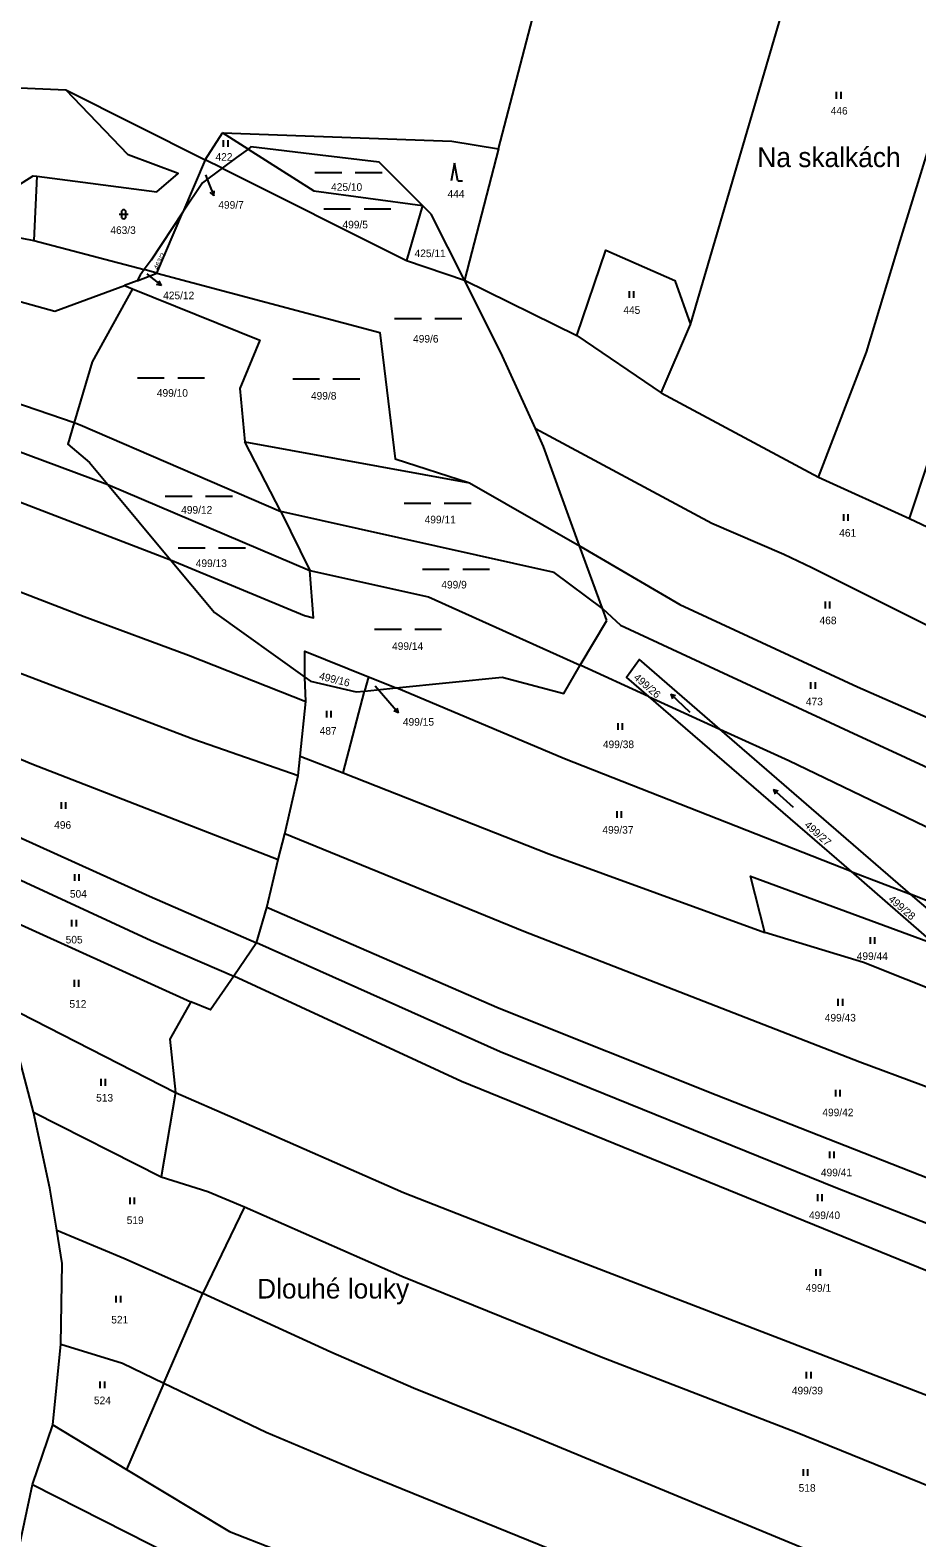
# Model space of a CAD drawing. Extents: x -751333 to -746055, y -1133395 to -1129777.
# Drawn here: x -748639.3 to -748441, y -1130763.6 to -1130426.4 of the extents above; entities that cross this region are included whole.
import ezdxf

# ---------------------------------------------------------------- set-up
doc = ezdxf.new("R2010")
doc.units = 0
for name, color, linetype in [('Hranice parcel', 7, 'Continuous'), ('Parcelní čísla', 7, 'Continuous'), ('Pop  PČ popisy', 7, 'Continuous'), ('Značky kultur', 7, 'Continuous')]:
    doc.layers.add(name, color=color, linetype=linetype)

msp = doc.modelspace()

# ---------------------------------------------------------------- linework, layer by layer
at = {"layer": 'Hranice parcel'}
for p, q in [((-748534.52, -1130452.93), (-748526.93, -1130423.75)), ((-748631.31, -1130439.73), (-748600.12, -1130455.36)), ((-748600.12, -1130455.36), (-748596.26, -1130449.29)), ((-748590.55, -1130452.94), (-748596.26, -1130449.29)), ((-748589.92, -1130452.46), (-748590.55, -1130452.94)), ((-748534.52, -1130452.93), (-748542.15, -1130482.28)), ((-748600.12, -1130455.36), (-748605.1, -1130467.06)), ((-748596.34, -1130457.26), (-748600.12, -1130455.36)), ((-748637.75, -1130459.01), (-748638.43, -1130473.4)), ((-748596.34, -1130457.26), (-748555.14, -1130477.91)), ((-748551.51, -1130465.56), (-748555.14, -1130477.91)), ((-748549.6, -1130467.48), (-748551.51, -1130465.56)), ((-748664.43, -1130468.41), (-748638.43, -1130473.4)), ((-748610.91, -1130480.71), (-748605.1, -1130467.06)), ((-748542.15, -1130482.28), (-748549.6, -1130467.48)), ((-748638.43, -1130473.4), (-748613.76, -1130479.92)), ((-748610.91, -1130480.71), (-748613.76, -1130479.92)), ((-748555.14, -1130477.91), (-748542.15, -1130482.28)), ((-748615.34, -1130482.41), (-748618.21, -1130483.5)), ((-748618.21, -1130483.5), (-748616.35, -1130484.25)), ((-748615.34, -1130482.41), (-748610.91, -1130480.71)), ((-748542.15, -1130482.28), (-748517.05, -1130494.67)), ((-748534, -1130498.43), (-748542.15, -1130482.28)), ((-748616.35, -1130484.25), (-748625.37, -1130500.52)), ((-748498.16, -1130507.52), (-748491.6, -1130492.22)), ((-748517.05, -1130494.67), (-748498.16, -1130507.52)), ((-748625.37, -1130500.52), (-748629.43, -1130514.15)), ((-748526.29, -1130515.48), (-748534, -1130498.43)), ((-748498.16, -1130507.52), (-748462.95, -1130526.39)), ((-748524.47, -1130519.52), (-748526.29, -1130515.48)), ((-748591.26, -1130518.45), (-748541.05, -1130527.62)), ((-748583.24, -1130534.05), (-748591.26, -1130518.45)), ((-748516.42, -1130541.69), (-748524.47, -1130519.52)), ((-748625.99, -1130523.1), (-748621.93, -1130527.97)), ((-748541.05, -1130527.62), (-748516.42, -1130541.69)), ((-748462.95, -1130526.39), (-748442.63, -1130535.63)), ((-748621.93, -1130527.97), (-748576.71, -1130547.24)), ((-748621.93, -1130527.97), (-748607.86, -1130544.88)), ((-748583.24, -1130534.05), (-748576.71, -1130547.24)), ((-748442.63, -1130535.63), (-748423.83, -1130544.43)), ((-748511.31, -1130555.77), (-748516.42, -1130541.69)), ((-748607.86, -1130544.88), (-748598.07, -1130556.63)), ((-748598.07, -1130556.63), (-748577.87, -1130571.1)), ((-748510.34, -1130558.44), (-748511.31, -1130555.77)), ((-748516.24, -1130568.44), (-748510.34, -1130558.44)), ((-748577.63, -1130576.56), (-748577.87, -1130571.1)), ((-748563.63, -1130571.01), (-748564.53, -1130574.23)), ((-748563.63, -1130571.01), (-748557.39, -1130573.5)), ((-748557.39, -1130573.5), (-748533.74, -1130571.13)), ((-748501.01, -1130575.41), (-748516.24, -1130568.44)), ((-748569.31, -1130592.51), (-748564.53, -1130574.23)), ((-748566.33, -1130574.4), (-748564.53, -1130574.23)), ((-748564.53, -1130574.23), (-748557.39, -1130573.5)), ((-748578.87, -1130588.74), (-748577.63, -1130576.56)), ((-748501.01, -1130575.41), (-748485.04, -1130582.73)), ((-748501.01, -1130575.41), (-748455.69, -1130614.55)), ((-748442.43, -1130619.67), (-748485.04, -1130582.73)), ((-748579.32, -1130593.13), (-748578.87, -1130588.74)), ((-748578.87, -1130588.74), (-748569.31, -1130592.51)), ((-748582.3, -1130606.18), (-748579.32, -1130593.13)), ((-748583.8, -1130611.89), (-748582.3, -1130606.18)), ((-748586.34, -1130622.61), (-748583.8, -1130611.89)), ((-748455.69, -1130614.55), (-748442.43, -1130619.67)), ((-748455.69, -1130614.55), (-748437.09, -1130630.78)), ((-748655.15, -1130620.24), (-748603.37, -1130643.75)), ((-748422.31, -1130636.78), (-748442.43, -1130619.67)), ((-748588.68, -1130630.55), (-748586.34, -1130622.61)), ((-748588.68, -1130630.55), (-748593.74, -1130637.98)), ((-748644.81, -1130644.52), (-748606.79, -1130664)), ((-748638.54, -1130668.43), (-748644.81, -1130644.52)), ((-748606.79, -1130664), (-748609.99, -1130682.87)), ((-748638.54, -1130668.43), (-748609.99, -1130682.87)), ((-748591.33, -1130689.59), (-748600.62, -1130708.93)), ((-748609.37, -1130729.04), (-748600.62, -1130708.93)), ((-748634.19, -1130738.36), (-748632.44, -1130720.29)), ((-748609.37, -1130729.04), (-748617.75, -1130748.36)), ((-748638.72, -1130751.72), (-748634.19, -1130738.36)), ((-748634.19, -1130738.36), (-748617.75, -1130748.36)), ((-748641.83, -1130766.14), (-748638.72, -1130751.72))]:
    msp.add_line(p, q, dxfattribs=at)
for points in [[(-748491.6, -1130492.22), (-748475.41, -1130437.09), (-748455.96, -1130370.65), (-748448.4, -1130345.8)], [(-748462.95, -1130526.39), (-748452.24, -1130498.41), (-748444.7, -1130473.49), (-748437.34, -1130449.55), (-748416.99, -1130383.85)], [(-748442.63, -1130535.63), (-748421.81, -1130472.84), (-748398.74, -1130399.57)], [(-748661.8, -1130465.15), (-748676.09, -1130437.74), (-748631.31, -1130439.73)], [(-748637.75, -1130459.01), (-748610.97, -1130462.51), (-748606.2, -1130458.41), (-748617.37, -1130454.25), (-748631.31, -1130439.73)], [(-748596.26, -1130449.29), (-748544.94, -1130451.18), (-748534.52, -1130452.93)], [(-748590.55, -1130452.94), (-748593.13, -1130454.85), (-748596.34, -1130457.26)], [(-748590.55, -1130452.94), (-748575.86, -1130462.3), (-748551.51, -1130465.56)], [(-748551.51, -1130465.56), (-748561.19, -1130455.89), (-748574.39, -1130454.31), (-748589.92, -1130452.46)], [(-748661.8, -1130465.15), (-748649.27, -1130465.67), (-748638.63, -1130458.96), (-748637.75, -1130459.01)], [(-748596.34, -1130457.26), (-748600.74, -1130460.52), (-748605.1, -1130467.06)], [(-748605.1, -1130467.06), (-748612.24, -1130477.79), (-748613.76, -1130479.92)], [(-748517.05, -1130494.67), (-748510.5, -1130475.55), (-748495.1, -1130482.38), (-748491.6, -1130492.22)], [(-748761.98, -1130479.13), (-748710.91, -1130496.25), (-748679.26, -1130506.7), (-748621.93, -1130527.97)], [(-748671.7, -1130478.68), (-748633.74, -1130489.24), (-748618.21, -1130483.5)], [(-748613.76, -1130479.92), (-748614.66, -1130481.2), (-748615.34, -1130482.41)], [(-748610.91, -1130480.71), (-748561.08, -1130494.01), (-748557.67, -1130522.23), (-748541.05, -1130527.62)], [(-748718.34, -1130483.88), (-748698.29, -1130490.59), (-748629.43, -1130514.15)], [(-748616.35, -1130484.25), (-748587.89, -1130495.71), (-748592.35, -1130506.49), (-748591.26, -1130518.45)], [(-748765.12, -1130487.78), (-748722.68, -1130502.34), (-748682.4, -1130515.73), (-748650.26, -1130528.57), (-748607.86, -1130544.88)], [(-748769.41, -1130499.53), (-748730.21, -1130516.5), (-748693.83, -1130531.8), (-748627.18, -1130557.56), (-748603.84, -1130566.17), (-748577.63, -1130576.56)], [(-748629.43, -1130514.15), (-748630.86, -1130518.95), (-748625.99, -1130523.1)], [(-748629.43, -1130514.15), (-748628.07, -1130514.66), (-748583.24, -1130534.05)], [(-748775.79, -1130517.06), (-748724.37, -1130538.57), (-748682.28, -1130555.19), (-748652.69, -1130565.92), (-748602.7, -1130584.94), (-748579.32, -1130593.13)], [(-748526.29, -1130515.48), (-748486.84, -1130536.66), (-748470.75, -1130543.61), (-748464.43, -1130546.57), (-748431.07, -1130563.27), (-748388.62, -1130583.11)], [(-748511.31, -1130555.77), (-748522.06, -1130547.66), (-748583.24, -1130534.05)], [(-748516.42, -1130541.69), (-748493.99, -1130554.85), (-748454.25, -1130573.29), (-748413.5, -1130591.12)], [(-748607.86, -1130544.88), (-748577.9, -1130557.3), (-748575.93, -1130557.81), (-748576.71, -1130547.24)], [(-748576.71, -1130547.24), (-748550.2, -1130553.1), (-748516.24, -1130568.44)], [(-748511.31, -1130555.77), (-748507.24, -1130559.45), (-748489.41, -1130567.71), (-748456.16, -1130583.21), (-748418.92, -1130600.37)], [(-748577.87, -1130571.1), (-748577.86, -1130565.29), (-748563.63, -1130571.01)], [(-748485.04, -1130582.73), (-748503.04, -1130567.18), (-748505.94, -1130571.16), (-748501.01, -1130575.41)], [(-748694.25, -1130568.39), (-748656.01, -1130583.36), (-748638.89, -1130590.49), (-748583.8, -1130611.89)], [(-748577.87, -1130571.1), (-748576.59, -1130572.02), (-748566.33, -1130574.4)], [(-748533.74, -1130571.13), (-748519.95, -1130574.72), (-748516.24, -1130568.44)], [(-748455.69, -1130614.55), (-748519.76, -1130589.35), (-748557.39, -1130573.5)], [(-748485.04, -1130582.73), (-748469.61, -1130589.74), (-748431.04, -1130608.33), (-748396.79, -1130621.28), (-748326.64, -1130647.59), (-748273.31, -1130666.87), (-748248.94, -1130675.02), (-748226.83, -1130683.61)], [(-748675.21, -1130591.78), (-748612.59, -1130620.06), (-748588.68, -1130630.55)], [(-748569.31, -1130592.51), (-748523.25, -1130610.65), (-748474.99, -1130628.2)], [(-748663.32, -1130606.39), (-748612.22, -1130630.04), (-748593.74, -1130637.98)], [(-748370.74, -1130688.16), (-748390.16, -1130680.44), (-748399.18, -1130677.54), (-748453.71, -1130657.26), (-748528.86, -1130627.98), (-748582.3, -1130606.18)], [(-748474.99, -1130628.2), (-748478.16, -1130615.62), (-748437.09, -1130630.78)], [(-748280.18, -1130682.27), (-748326.88, -1130664.57), (-748359.23, -1130651.59), (-748396.02, -1130637.54), (-748426.83, -1130625.94), (-748442.43, -1130619.67)], [(-748340.95, -1130721.23), (-748371.81, -1130709.41), (-748485.85, -1130664.58), (-748534.39, -1130645.25), (-748586.34, -1130622.61)], [(-748414.36, -1130650.31), (-748452.93, -1130634.95), (-748474.99, -1130628.2)], [(-748337.1, -1130732.95), (-748347.47, -1130729.08), (-748459.12, -1130685.32), (-748534.17, -1130654.92), (-748588.68, -1130630.55)], [(-748593.74, -1130637.98), (-748598.96, -1130645.55), (-748603.37, -1130643.75)], [(-748332.9, -1130745.74), (-748359.6, -1130735.19), (-748427.81, -1130708.36), (-748542.83, -1130661.55), (-748593.74, -1130637.98)], [(-748603.37, -1130643.75), (-748608.06, -1130652.05), (-748606.79, -1130664)], [(-748606.79, -1130664), (-748593.41, -1130669.82), (-748555.79, -1130686.41), (-748521.14, -1130699.97), (-748463.67, -1130722.09), (-748402.55, -1130745.71), (-748322.49, -1130777.44)], [(-748633.32, -1130694.84), (-748634.87, -1130685.4), (-748638.54, -1130668.43)], [(-748609.99, -1130682.87), (-748599.51, -1130686.16), (-748591.33, -1130689.59)], [(-748591.33, -1130689.59), (-748556.18, -1130705.09), (-748511.54, -1130723.13), (-748468.11, -1130739.92), (-748424.93, -1130757.48), (-748407.79, -1130764.49), (-748381.4, -1130774.63), (-748330.32, -1130793.51), (-748323.6, -1130795.85)], [(-748633.32, -1130694.84), (-748618.36, -1130701.09), (-748600.62, -1130708.93)], [(-748632.44, -1130720.29), (-748632.1, -1130702.29), (-748633.32, -1130694.84)], [(-748600.62, -1130708.93), (-748572.02, -1130722.05), (-748553.57, -1130730.11), (-748529.63, -1130739.69), (-748429.06, -1130781.38), (-748394.01, -1130795.35), (-748336, -1130816.73)], [(-748632.44, -1130720.29), (-748618.62, -1130724.53), (-748609.37, -1130729.04)], [(-748609.37, -1130729.04), (-748586.47, -1130739.97), (-748565.25, -1130748.92), (-748478.86, -1130784.11), (-748430.59, -1130803.91), (-748354.99, -1130834.29)], [(-748617.75, -1130748.36), (-748594.66, -1130762.19), (-748574.85, -1130769.98), (-748508.41, -1130796.48), (-748448.56, -1130820.81), (-748391.34, -1130844.41), (-748350.77, -1130860.5)], [(-748638.72, -1130751.72), (-748602.16, -1130770.3), (-748522.97, -1130802.41), (-748472.42, -1130822.39), (-748429.14, -1130840.54), (-748407.16, -1130849.74), (-748367.71, -1130867.32)]]:
    msp.add_lwpolyline(points, dxfattribs=at)
at = {"layer": 'Pop  PČ popisy'}
for p, q in [((-748600.09, -1130458.74), (-748599.31, -1130460.66)), ((-748599.31, -1130460.66), (-748598.186, -1130463.442)), ((-748598.186, -1130463.442), (-748599.025, -1130462.702)), ((-748598.186, -1130463.442), (-748598.097, -1130462.326)), ((-748613.2, -1130480.86), (-748612.28, -1130481.59)), ((-748612.28, -1130481.59), (-748609.915, -1130483.438)), ((-748609.915, -1130483.438), (-748611.013, -1130483.216)), ((-748609.915, -1130483.438), (-748610.396, -1130482.426)), ((-748562.13, -1130573), (-748558.86, -1130576.82)), ((-748558.86, -1130576.82), (-748556.891, -1130579.085)), ((-748556.891, -1130579.085), (-748557.17, -1130578.001)), ((-748556.891, -1130579.085), (-748557.926, -1130578.658))]:
    msp.add_line(p, q, dxfattribs=at)
at = {"layer": 'Značky kultur'}
for p, q in [((-748458.931, -1130441.68), (-748458.931, -1130440.18)), ((-748457.93, -1130441.68), (-748457.93, -1130440.18)), ((-748596.011, -1130452.49), (-748596.011, -1130450.99)), ((-748595.01, -1130452.49), (-748595.01, -1130450.99)), ((-748544.37, -1130456.08), (-748545.12, -1130460.08)), ((-748543.62, -1130460.08), (-748544.37, -1130456.08)), ((-748575.589, -1130458.19), (-748569.589, -1130458.19)), ((-748566.589, -1130458.19), (-748560.589, -1130458.19)), ((-748543.62, -1130460.08), (-748542.624, -1130460.08)), ((-748573.609, -1130466.35), (-748567.609, -1130466.35)), ((-748564.609, -1130466.35), (-748558.609, -1130466.35)), ((-748619.361, -1130467.541), (-748617.359, -1130467.541)), ((-748618.861, -1130467.041), (-748618.861, -1130468.042)), ((-748617.859, -1130468.042), (-748617.859, -1130467.041)), ((-748505.261, -1130486.27), (-748505.261, -1130484.77)), ((-748504.26, -1130486.27), (-748504.26, -1130484.77)), ((-748557.769, -1130490.84), (-748551.769, -1130490.84)), ((-748548.769, -1130490.84), (-748542.769, -1130490.84)), ((-748615.269, -1130504.15), (-748609.269, -1130504.15)), ((-748606.269, -1130504.15), (-748600.269, -1130504.15)), ((-748580.559, -1130504.37), (-748574.559, -1130504.37)), ((-748571.559, -1130504.37), (-748565.559, -1130504.37)), ((-748609.059, -1130530.57), (-748603.059, -1130530.57)), ((-748600.059, -1130530.57), (-748594.059, -1130530.57)), ((-748555.669, -1130532.17), (-748549.669, -1130532.17)), ((-748546.669, -1130532.17), (-748540.669, -1130532.17)), ((-748457.331, -1130536.12), (-748457.331, -1130534.62)), ((-748456.33, -1130536.12), (-748456.33, -1130534.62)), ((-748606.149, -1130542.13), (-748600.149, -1130542.13)), ((-748597.149, -1130542.13), (-748591.149, -1130542.13)), ((-748551.549, -1130546.92), (-748545.549, -1130546.92)), ((-748542.549, -1130546.92), (-748536.549, -1130546.92)), ((-748461.411, -1130555.7), (-748461.411, -1130554.2)), ((-748460.41, -1130555.7), (-748460.41, -1130554.2)), ((-748562.259, -1130560.36), (-748556.259, -1130560.36)), ((-748553.259, -1130560.36), (-748547.259, -1130560.36)), ((-748491.643, -1130578.988), (-748496.031, -1130574.896)), ((-748496.031, -1130574.896), (-748495.658, -1130575.929)), ((-748496.031, -1130574.896), (-748494.974, -1130575.196)), ((-748464.671, -1130573.74), (-748464.671, -1130572.24)), ((-748463.67, -1130573.74), (-748463.67, -1130572.24)), ((-748572.941, -1130580.1), (-748572.941, -1130578.6)), ((-748571.94, -1130580.1), (-748571.94, -1130578.6)), ((-748507.791, -1130582.87), (-748507.791, -1130581.37)), ((-748506.79, -1130582.87), (-748506.79, -1130581.37)), ((-748468.578, -1130600.25), (-748473.036, -1130596.235)), ((-748473.036, -1130596.235), (-748472.646, -1130597.261)), ((-748473.036, -1130596.235), (-748471.975, -1130596.516)), ((-748632.291, -1130600.58), (-748632.291, -1130599.08)), ((-748631.29, -1130600.58), (-748631.29, -1130599.08)), ((-748508.031, -1130602.56), (-748508.031, -1130601.06)), ((-748507.03, -1130602.56), (-748507.03, -1130601.06)), ((-748629.281, -1130616.67), (-748629.281, -1130615.17)), ((-748628.28, -1130616.67), (-748628.28, -1130615.17)), ((-748629.941, -1130626.91), (-748629.941, -1130625.41)), ((-748628.94, -1130626.91), (-748628.94, -1130625.41)), ((-748451.361, -1130630.74), (-748451.361, -1130629.24)), ((-748450.36, -1130630.74), (-748450.36, -1130629.24)), ((-748629.371, -1130640.34), (-748629.371, -1130638.84)), ((-748628.37, -1130640.34), (-748628.37, -1130638.84)), ((-748458.551, -1130644.59), (-748458.551, -1130643.09)), ((-748457.55, -1130644.59), (-748457.55, -1130643.09)), ((-748623.391, -1130662.49), (-748623.391, -1130660.99)), ((-748622.39, -1130662.49), (-748622.39, -1130660.99)), ((-748459.111, -1130664.9), (-748459.111, -1130663.4)), ((-748458.11, -1130664.9), (-748458.11, -1130663.4)), ((-748460.461, -1130678.72), (-748460.461, -1130677.22)), ((-748459.46, -1130678.72), (-748459.46, -1130677.22)), ((-748616.921, -1130689.02), (-748616.921, -1130687.52)), ((-748615.92, -1130689.02), (-748615.92, -1130687.52)), ((-748463.131, -1130688.29), (-748463.131, -1130686.79)), ((-748462.13, -1130688.29), (-748462.13, -1130686.79)), ((-748463.531, -1130705.04), (-748463.531, -1130703.54)), ((-748462.53, -1130705.04), (-748462.53, -1130703.54)), ((-748620.011, -1130710.98), (-748620.011, -1130709.48)), ((-748619.01, -1130710.98), (-748619.01, -1130709.48)), ((-748465.621, -1130728), (-748465.621, -1130726.5)), ((-748464.62, -1130728), (-748464.62, -1130726.5)), ((-748623.591, -1130730.19), (-748623.591, -1130728.69)), ((-748622.59, -1130730.19), (-748622.59, -1130728.69)), ((-748466.341, -1130749.77), (-748466.341, -1130748.27)), ((-748465.34, -1130749.77), (-748465.34, -1130748.27))]:
    msp.add_line(p, q, dxfattribs=at)
for centre, start, end in [((-748618.36, -1130467.041), 0, 180), ((-748618.36, -1130468.041), 180, 359.98789)]:
    msp.add_arc(centre, 0.5, start, end, dxfattribs=at)

# ---------------------------------------------------------------- texts
at = {"layer": 'Parcelní čísla'}
for s, p in [('446', (-748460.25, -1130445.23)), ('422', (-748597.82, -1130455.56)), ('425/10', (-748571.97, -1130462.29)), ('444', (-748545.93, -1130463.84)), ('499/7', (-748597.19, -1130466.288)), ('463/3', (-748621.34, -1130471.94)), ('499/5', (-748569.42, -1130470.7)), ('425/11', (-748553.3, -1130477.13)), ('425/12', (-748609.53, -1130486.548)), ('445', (-748506.62, -1130489.82)), ('499/6', (-748553.64, -1130496.24)), ('499/10', (-748610.94, -1130508.36)), ('499/8', (-748576.47, -1130509)), ('499/12', (-748605.5, -1130534.52)), ('499/11', (-748551.05, -1130536.69)), ('461', (-748458.34, -1130539.67)), ('499/13', (-748602.24, -1130546.46)), ('499/9', (-748547.32, -1130551.25)), ('468', (-748462.74, -1130559.25)), ('499/14', (-748558.34, -1130565)), ('473', (-748465.79, -1130577.41)), ('499/15', (-748555.91, -1130581.948)), ('487', (-748574.53, -1130583.95)), ('499/38', (-748511.18, -1130586.97)), ('496', (-748633.9, -1130605.01)), ('499/37', (-748511.3, -1130606.11)), ('504', (-748630.39, -1130620.42)), ('505', (-748631.33, -1130630.67)), ('499/44', (-748454.42, -1130634.35)), ('512', (-748630.49, -1130645.05)), ('499/43', (-748461.57, -1130648.13)), ('513', (-748624.52, -1130666.04)), ('499/42', (-748462.11, -1130669.32)), ('499/41', (-748462.43, -1130682.76)), ('519', (-748617.68, -1130693.44)), ('499/40', (-748465.1, -1130692.33)), ('499/1', (-748465.84, -1130708.59)), ('521', (-748621.13, -1130715.69)), ('499/39', (-748468.93, -1130731.55)), ('524', (-748625.01, -1130733.74)), ('518', (-748467.41, -1130753.32))]:
    msp.add_text(s, height=1.7, dxfattribs=at).set_placement(p)
for s, height, rotation, p in [('463/2', 1.14, 63, (-748610.706, -1130480.089)), ('499/16', 1.7, 346, (-748574.775, -1130571.564)), ('499/26', 1.7, 319, (-748504.447, -1130571.401)), ('499/27', 1.7, 318, (-748466.258, -1130604.381)), ('499/28', 1.7, 319, (-748447.477, -1130621.011))]:
    msp.add_text(s, height=height, rotation=rotation, dxfattribs=at).set_placement(p)
at = {"layer": 'Pop  PČ popisy'}
for s, p in [('Na skalkách', (-748476.654, -1130456.99)), ('Dlouhé louky', (-748588.521, -1130710.1))]:
    msp.add_text(s, height=4.4, dxfattribs=at).set_placement(p)

doc.saveas('drawing.dxf')
